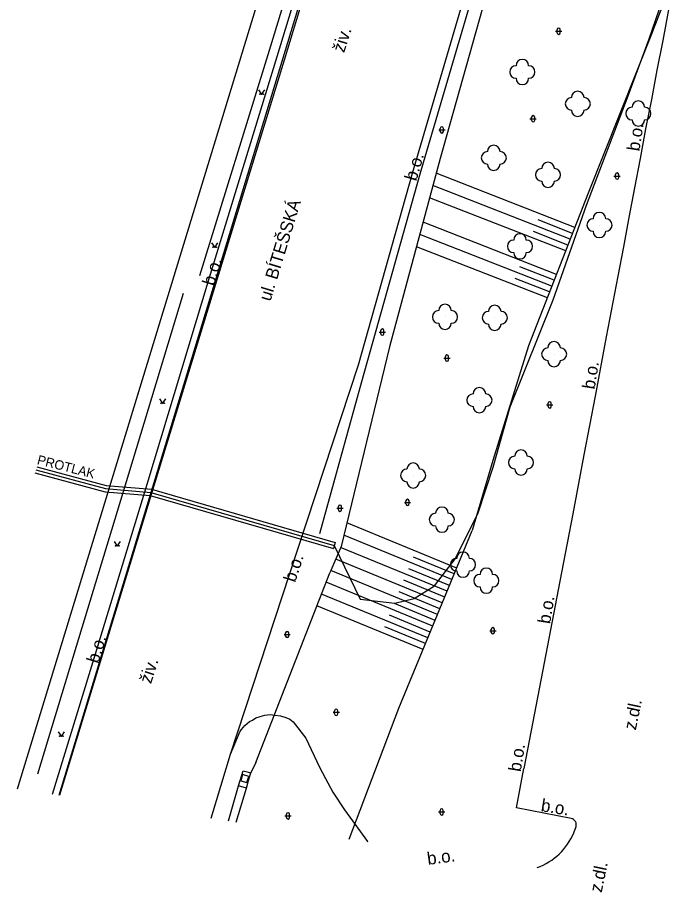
# Model space of a CAD drawing. Extents: x -601602 to -600882, y -1162594 to -1161950.
# Drawn here: x -601602.4 to -601549.7, y -1162371.2 to -1162301.7 of the extents above; entities that cross this region are included whole.
import ezdxf

# ---------------------------------------------------------------- set-up
doc = ezdxf.new("R2010")
doc.units = 0
for name, color, linetype in [('G_ZNACKY', 7, 'Continuous'), ('VRSTVA 1', 7, 'Continuous'), ('Vrstva 13', 7, 'Continuous'), ('Vrstva 14', 7, 'Continuous'), ('Vrstva 15 (Construction)', 7, 'Continuous'), ('Vrstva 16', 7, 'Continuous'), ('VRSTVA 3', 7, 'Continuous'), ('VRSTVA 5', 7, 'Continuous'), ('Vrstva 6', 7, 'Continuous'), ('Vrstva 8', 7, 'Continuous')]:
    doc.layers.add(name, color=color, linetype=linetype)

msp = doc.modelspace()

# ---------------------------------------------------------------- linework, layer by layer
at = {"layer": 'G_ZNACKY'}
for p, q in [((-601584.55, -1162361.838), (-601584.695, -1162362.317)), ((-601584.071, -1162361.983), (-601584.55, -1162361.838)), ((-601584.216, -1162362.462), (-601584.071, -1162361.983)), ((-601584.695, -1162362.317), (-601584.216, -1162362.462))]:
    msp.add_line(p, q, dxfattribs=at)
at = {"layer": 'VRSTVA 1'}
msp.add_lwpolyline([(-601600.969, -1162337.616), (-601595.43, -1162339.11), (-601591.84, -1162339.41), (-601577.27, -1162343.63), (-601575.23, -1162347.89), (-601572.47, -1162348.22), (-601570.93, -1162347.84), (-601569.32, -1162346.84), (-601567.66, -1162344.67), (-601565.85, -1162341.04), (-601564.67, -1162337.39), (-601563.31, -1162332.6), (-601559.89, -1162324.11), (-601557.24, -1162316.58), (-601553.94, -1162307.88), (-601552.28, -1162303.36), (-601551.21, -1162300.27)], dxfattribs=at)
at = {"layer": 'Vrstva 13'}
for p, q in [((-601602.424, -1162362.969), (-601579.44, -1162287.64)), ((-601599.105, -1162363.472), (-601576.28, -1162288.19)), ((-601576.41, -1162289.16), (-601581.25, -1162305.05)), ((-601571.05, -1162314.04), (-601566.41, -1162298.21)), ((-601550.65, -1162300.61), (-601551.19, -1162303.49)), ((-601551.19, -1162303.49), (-601551.66, -1162305.84)), ((-601581.25, -1162305.05), (-601586.6, -1162322.52)), ((-601551.66, -1162305.84), (-601552.09, -1162308.18)), ((-601552.09, -1162308.18), (-601552.55, -1162310.51)), ((-601552.55, -1162310.51), (-601552.99, -1162312.87)), ((-601552.99, -1162312.87), (-601553.43, -1162315.2)), ((-601575.35, -1162329.26), (-601571.05, -1162314.04)), ((-601553.43, -1162315.2), (-601553.88, -1162317.55)), ((-601553.88, -1162317.55), (-601554.32, -1162319.88)), ((-601554.32, -1162319.88), (-601554.76, -1162322.22)), ((-601554.76, -1162322.22), (-601555.68, -1162327.05)), ((-601586.6, -1162322.52), (-601591.59, -1162338.89)), ((-601555.68, -1162327.05), (-601556.57, -1162331.75)), ((-601580.79, -1162345.84), (-601575.35, -1162329.26)), ((-601556.57, -1162331.75), (-601557.46, -1162336.42)), ((-601557.46, -1162336.42), (-601558.34, -1162341.1)), ((-601591.59, -1162338.89), (-601599.094, -1162363.473)), ((-601558.34, -1162341.1), (-601559.24, -1162345.78)), ((-601585.52, -1162360.207), (-601580.79, -1162345.84)), ((-601559.24, -1162345.78), (-601560.6, -1162352.95)), ((-601560.6, -1162352.95), (-601561.5, -1162357.64)), ((-601583.491, -1162357.336), (-601583.159, -1162357.214)), ((-601583.159, -1162357.214), (-601582.776, -1162357.118)), ((-601582.776, -1162357.118), (-601582.375, -1162357.065)), ((-601582.375, -1162357.065), (-601581.991, -1162357.1)), ((-601581.991, -1162357.1), (-601581.547, -1162357.161)), ((-601581.547, -1162357.161), (-601581.128, -1162357.301)), ((-601584.371, -1162357.929), (-601584.197, -1162357.772)), ((-601584.197, -1162357.772), (-601583.996, -1162357.615)), ((-601583.996, -1162357.615), (-601583.77, -1162357.501)), ((-601583.77, -1162357.501), (-601583.491, -1162357.336)), ((-601581.128, -1162357.301), (-601580.814, -1162357.432)), ((-601580.814, -1162357.432), (-601580.53, -1162357.63)), ((-601580.53, -1162357.63), (-601579.54, -1162358.93)), ((-601561.5, -1162357.64), (-601562.22, -1162361.36)), ((-601585.51, -1162360.21), (-601584.75, -1162358.39)), ((-601584.75, -1162358.39), (-601584.65, -1162358.243)), ((-601584.65, -1162358.243), (-601584.371, -1162357.929)), ((-601579.54, -1162358.93), (-601578.452, -1162361.252)), ((-601587.055, -1162365.298), (-601585.51, -1162360.21)), ((-601578.452, -1162361.252), (-601577.963, -1162362.142)), ((-601562.81, -1162364.48), (-601562.22, -1162361.36)), ((-601584.88, -1162362.73), (-601584.52, -1162361.54)), ((-601584.52, -1162361.54), (-601583.91, -1162361.69)), ((-601584.083, -1162362.309), (-601583.91, -1162361.69)), ((-601585.662, -1162365.509), (-601584.88, -1162362.73)), ((-601584.25, -1162362.91), (-601584.88, -1162362.73)), ((-601584.25, -1162362.91), (-601584.083, -1162362.309)), ((-601577.963, -1162362.142), (-601577.388, -1162363.223)), ((-601585.053, -1162365.602), (-601584.25, -1162362.91)), ((-601577.388, -1162363.223), (-601576.464, -1162364.636)), ((-601576.464, -1162364.636), (-601575.627, -1162365.804)), ((-601558.47, -1162365.33), (-601562.81, -1162364.48)), ((-601575.627, -1162365.804), (-601574.633, -1162367.147)), ((-601558.26, -1162366.46), (-601558.08, -1162365.97)), ((-601574.633, -1162367.147), (-601574.602, -1162367.185))]:
    msp.add_line(p, q, dxfattribs=at)
for centre, radius, start, end in [((-601558.541, -1162365.812), 0.487, 341.0513, 81.66287), ((-601562.827, -1162364.569), 4.943, 289.71035, 337.51017)]:
    msp.add_arc(centre, radius, start, end, dxfattribs=at)
at = {"layer": 'Vrstva 14'}
for p, q in [((-601564.31, -1162296.62), (-601568.86, -1162312.86)), ((-601559.703, -1162302.757), (-601559.203, -1162302.757)), ((-601559.578, -1162302.882), (-601559.578, -1162302.632)), ((-601559.328, -1162302.882), (-601559.328, -1162302.632)), ((-601552.04, -1162302.86), (-601557.11, -1162315.64)), ((-601561.735, -1162309.71), (-601561.235, -1162309.71)), ((-601561.61, -1162309.835), (-601561.61, -1162309.585)), ((-601561.36, -1162309.835), (-601561.36, -1162309.585)), ((-601568.982, -1162310.602), (-601568.482, -1162310.602)), ((-601568.857, -1162310.727), (-601568.857, -1162310.477)), ((-601568.607, -1162310.727), (-601568.607, -1162310.477)), ((-601568.86, -1162312.86), (-601572.88, -1162327.83)), ((-601558.172, -1162318.355), (-601569.18, -1162314.05)), ((-601555.068, -1162314.269), (-601554.568, -1162314.269)), ((-601554.943, -1162314.394), (-601554.943, -1162314.144)), ((-601554.693, -1162314.394), (-601554.693, -1162314.144)), ((-601558.536, -1162319.286), (-601569.441, -1162315.022)), ((-601558.9, -1162320.218), (-601569.702, -1162315.994)), ((-601557.11, -1162315.64), (-601561.85, -1162327.76)), ((-601559.629, -1162322.08), (-601570.223, -1162317.937)), ((-601558.354, -1162318.821), (-601561.091, -1162317.75)), ((-601559.993, -1162323.012), (-601570.484, -1162318.909)), ((-601558.718, -1162319.752), (-601561.455, -1162318.682)), ((-601560.357, -1162323.943), (-601570.745, -1162319.881)), ((-601559.811, -1162322.546), (-601562.548, -1162321.476)), ((-601560.175, -1162323.477), (-601562.912, -1162322.407)), ((-601573.582, -1162326.794), (-601573.582, -1162326.544)), ((-601573.332, -1162326.794), (-601573.332, -1162326.544)), ((-601573.707, -1162326.669), (-601573.207, -1162326.669)), ((-601572.88, -1162327.83), (-601576.74, -1162343.71)), ((-601561.85, -1162327.76), (-601564.68, -1162336.86)), ((-601568.456, -1162328.863), (-601568.456, -1162328.613)), ((-601568.206, -1162328.863), (-601568.206, -1162328.613)), ((-601568.581, -1162328.738), (-601568.081, -1162328.738)), ((-601560.418, -1162332.451), (-601559.918, -1162332.451)), ((-601560.293, -1162332.576), (-601560.293, -1162332.326)), ((-601560.043, -1162332.576), (-601560.043, -1162332.326)), ((-601564.68, -1162336.86), (-601566.32, -1162342.43)), ((-601571.711, -1162340.204), (-601571.211, -1162340.204)), ((-601571.586, -1162340.329), (-601571.586, -1162340.079)), ((-601571.336, -1162340.329), (-601571.336, -1162340.079)), ((-601577.073, -1162340.664), (-601576.573, -1162340.664)), ((-601576.948, -1162340.789), (-601576.948, -1162340.539)), ((-601576.698, -1162340.789), (-601576.698, -1162340.539)), ((-601567.552, -1162345.418), (-601576.281, -1162341.82)), ((-601572.14, -1162356.55), (-601566.32, -1162342.43)), ((-601567.933, -1162346.343), (-601576.52, -1162342.804)), ((-601576.74, -1162343.71), (-601577.63, -1162345.8)), ((-601568.314, -1162347.267), (-601576.77, -1162343.781)), ((-601567.742, -1162345.881), (-601570.98, -1162344.546)), ((-601568.695, -1162348.192), (-601577.162, -1162344.702)), ((-601583.5, -1162360.87), (-601577.63, -1162345.8)), ((-601569.076, -1162349.117), (-601577.554, -1162345.622)), ((-601568.123, -1162346.805), (-601571.361, -1162345.471)), ((-601569.457, -1162350.041), (-601577.923, -1162346.551)), ((-601568.504, -1162347.73), (-601571.742, -1162346.395)), ((-601568.886, -1162348.654), (-601572.123, -1162347.32)), ((-601569.838, -1162350.966), (-601578.286, -1162347.484)), ((-601570.219, -1162351.89), (-601578.649, -1162348.415)), ((-601569.267, -1162349.579), (-601572.504, -1162348.245)), ((-601569.648, -1162350.503), (-601572.885, -1162349.169)), ((-601570.029, -1162351.428), (-601573.266, -1162350.094)), ((-601581.265, -1162350.702), (-601580.765, -1162350.702)), ((-601581.14, -1162350.827), (-601581.14, -1162350.577)), ((-601580.89, -1162350.827), (-601580.89, -1162350.577)), ((-601564.933, -1162350.407), (-601564.433, -1162350.407)), ((-601564.808, -1162350.532), (-601564.808, -1162350.282)), ((-601564.558, -1162350.532), (-601564.558, -1162350.282)), ((-601577.372, -1162356.885), (-601576.872, -1162356.885)), ((-601577.247, -1162357.01), (-601577.247, -1162356.76)), ((-601576.997, -1162357.01), (-601576.997, -1162356.76)), ((-601576.082, -1162366.961), (-601572.14, -1162356.55)), ((-601583.5, -1162360.87), (-601583.91, -1162361.69)), ((-601568.991, -1162364.805), (-601568.491, -1162364.805)), ((-601568.866, -1162364.93), (-601568.866, -1162364.68)), ((-601568.616, -1162364.93), (-601568.616, -1162364.68)), ((-601581.191, -1162365.114), (-601580.691, -1162365.114)), ((-601581.066, -1162365.239), (-601581.066, -1162364.989)), ((-601580.816, -1162365.239), (-601580.816, -1162364.989))]:
    msp.add_line(p, q, dxfattribs=at)
for centre in [(-601562.34, -1162306), (-601557.94, -1162308.53), (-601553.13, -1162309.3), (-601564.61, -1162312.82), (-601560.3, -1162314.17), (-601556.22, -1162318.16), (-601562.53, -1162319.85), (-601568.48, -1162325.46), (-601564.53, -1162325.53), (-601559.82, -1162328.42), (-601565.75, -1162332.08), (-601562.45, -1162337.03), (-601571.01, -1162338.06), (-601568.73, -1162341.57), (-601567.05, -1162345.15), (-601565.2, -1162346.42)]:
    msp.add_circle(centre, 0.0005, dxfattribs=at)
for centre, radius, start, end in [((-601523.195, -1162313.204), 30.643, 133.91725, 160.27226), ((-601559.453, -1162302.632), 0.125, 0, 179.99999), ((-601559.453, -1162302.882), 0.125, 179.99999, 359.99999), ((-601562.34, -1162305.5), 0.5, 0, 179.99999), ((-601562.84, -1162306), 0.5, 89.99999, 269.99999), ((-601561.84, -1162306), 0.5, 270, 89.99999), ((-601562.34, -1162306.5), 0.5, 179.99999, 359.99999), ((-601557.94, -1162308.03), 0.5, 0, 179.99999), ((-601558.44, -1162308.53), 0.5, 89.99999, 269.99999), ((-601557.44, -1162308.53), 0.5, 270, 89.99999), ((-601553.13, -1162308.8), 0.5, 0, 179.99999), ((-601557.94, -1162309.03), 0.5, 179.99999, 359.99999), ((-601553.63, -1162309.3), 0.5, 89.99999, 269.99999), ((-601552.63, -1162309.3), 0.5, 270, 89.99999), ((-601561.485, -1162309.585), 0.125, 0, 179.99999), ((-601561.485, -1162309.835), 0.125, 179.99999, 359.99999), ((-601553.13, -1162309.8), 0.5, 179.99999, 359.99999), ((-601568.731, -1162310.477), 0.125, 0, 179.99999), ((-601568.731, -1162310.727), 0.125, 179.99999, 359.99999), ((-601564.61, -1162312.32), 0.5, 0, 179.99999), ((-601565.11, -1162312.82), 0.5, 89.99999, 269.99999), ((-601564.11, -1162312.82), 0.5, 270, 89.99999), ((-601564.61, -1162313.32), 0.5, 179.99999, 359.99999), ((-601560.3, -1162313.67), 0.5, 0, 179.99999), ((-601560.8, -1162314.17), 0.5, 89.99999, 269.99999), ((-601559.8, -1162314.17), 0.5, 270, 89.99999), ((-601554.818, -1162314.144), 0.125, 0, 179.99999), ((-601560.3, -1162314.67), 0.5, 179.99999, 359.99999), ((-601554.818, -1162314.394), 0.125, 179.99999, 359.99999), ((-601556.22, -1162317.66), 0.5, 0, 179.99999), ((-601556.72, -1162318.16), 0.5, 89.99999, 269.99999), ((-601555.72, -1162318.16), 0.5, 270, 89.99999), ((-601562.53, -1162319.35), 0.5, 0, 179.99999), ((-601556.22, -1162318.66), 0.5, 179.99999, 359.99999), ((-601563.03, -1162319.85), 0.5, 89.99999, 269.99999), ((-601562.03, -1162319.85), 0.5, 270, 89.99999), ((-601562.53, -1162320.35), 0.5, 179.99999, 359.99999), ((-601568.48, -1162324.96), 0.5, 0, 179.99999), ((-601564.53, -1162325.03), 0.5, 0, 179.99999), ((-601568.98, -1162325.46), 0.5, 89.99999, 269.99999), ((-601567.98, -1162325.46), 0.5, 270, 89.99999), ((-601565.03, -1162325.53), 0.5, 89.99999, 269.99999), ((-601564.03, -1162325.53), 0.5, 270, 89.99999), ((-601573.457, -1162326.544), 0.125, 0, 179.99999), ((-601568.48, -1162325.96), 0.5, 179.99999, 359.99999), ((-601564.53, -1162326.03), 0.5, 179.99999, 359.99999), ((-601573.457, -1162326.794), 0.125, 179.99999, 359.99999), ((-601560.32, -1162328.42), 0.5, 89.99999, 269.99999), ((-601559.82, -1162327.92), 0.5, 0, 179.99999), ((-601559.32, -1162328.42), 0.5, 270, 89.99999), ((-601568.331, -1162328.613), 0.125, 0, 179.99999), ((-601568.331, -1162328.863), 0.125, 179.99999, 359.99999), ((-601559.82, -1162328.92), 0.5, 179.99999, 359.99999), ((-601565.75, -1162331.58), 0.5, 0, 179.99999), ((-601566.25, -1162332.08), 0.5, 89.99999, 269.99999), ((-601565.25, -1162332.08), 0.5, 270, 89.99999), ((-601565.75, -1162332.58), 0.5, 179.99999, 359.99999), ((-601560.168, -1162332.326), 0.125, 0, 179.99999), ((-601560.168, -1162332.576), 0.125, 179.99999, 359.99999), ((-601562.45, -1162336.53), 0.5, 0, 179.99999), ((-601562.95, -1162337.03), 0.5, 89.99999, 269.99999), ((-601561.95, -1162337.03), 0.5, 270, 89.99999), ((-601571.51, -1162338.06), 0.5, 89.99999, 269.99999), ((-601571.01, -1162337.56), 0.5, 0, 179.99999), ((-601570.51, -1162338.06), 0.5, 270, 89.99999), ((-601562.45, -1162337.53), 0.5, 179.99999, 359.99999), ((-601571.01, -1162338.56), 0.5, 179.99999, 359.99999), ((-601576.823, -1162340.539), 0.125, 0, 179.99999), ((-601571.46, -1162340.081), 0.125, 0, 179.99999), ((-601571.46, -1162340.331), 0.125, 179.99999, 359.99999), ((-601576.823, -1162340.789), 0.125, 179.99999, 359.99999), ((-601569.23, -1162341.57), 0.5, 89.99999, 269.99999), ((-601568.73, -1162341.07), 0.5, 0, 179.99999), ((-601568.23, -1162341.57), 0.5, 270, 89.99999), ((-601568.73, -1162342.07), 0.5, 179.99999, 359.99999), ((-601567.55, -1162345.15), 0.5, 89.99999, 269.99999), ((-601567.05, -1162344.65), 0.5, 0, 179.99999), ((-601566.55, -1162345.15), 0.5, 270, 89.99999), ((-601567.05, -1162345.65), 0.5, 179.99999, 359.99999), ((-601565.7, -1162346.42), 0.5, 89.99999, 269.99999), ((-601565.2, -1162345.92), 0.5, 0, 179.99999), ((-601564.7, -1162346.42), 0.5, 270, 89.99999), ((-601565.2, -1162346.92), 0.5, 179.99999, 359.99999), ((-601564.683, -1162350.282), 0.125, 0, 179.99999), ((-601581.015, -1162350.577), 0.125, 0, 179.99999), ((-601581.015, -1162350.827), 0.125, 179.99999, 359.99999), ((-601564.683, -1162350.532), 0.125, 179.99999, 359.99999), ((-601577.122, -1162356.76), 0.125, 0, 179.99999), ((-601577.122, -1162357.01), 0.125, 179.99999, 359.99999), ((-601580.941, -1162364.989), 0.125, 0, 179.99999), ((-601568.741, -1162364.68), 0.125, 0, 179.99999), ((-601580.941, -1162365.239), 0.125, 179.99999, 359.99999), ((-601568.741, -1162364.93), 0.125, 179.99999, 359.99999)]:
    msp.add_arc(centre, radius, start, end, dxfattribs=at)
at = {"layer": 'VRSTVA 3'}
for points in [[(-601583.299, -1162307.412), (-601583.049, -1162307.787), (-601582.799, -1162307.412)], [(-601587.02, -1162319.57), (-601586.77, -1162319.945), (-601586.52, -1162319.57)], [(-601591.155, -1162331.975), (-601590.905, -1162332.35), (-601590.655, -1162331.975)], [(-601594.758, -1162343.308), (-601594.508, -1162343.683), (-601594.258, -1162343.308)], [(-601599.188, -1162358.426), (-601598.938, -1162358.801), (-601598.688, -1162358.426)]]:
    msp.add_lwpolyline(points, dxfattribs=at)
for centre in [(-601583.174, -1162307.762), (-601582.924, -1162307.762), (-601586.895, -1162319.92), (-601586.645, -1162319.92), (-601591.03, -1162332.325), (-601590.78, -1162332.325), (-601594.633, -1162343.658), (-601594.383, -1162343.658), (-601599.063, -1162358.776), (-601598.813, -1162358.776)]:
    msp.add_circle(centre, 0.025, dxfattribs=at)
at = {"layer": 'VRSTVA 5'}
msp.add_line((-601577.2, -1162343.39), (-601577.34, -1162343.87), dxfattribs=at)
for points in [[(-601600.969, -1162337.616), (-601595.43, -1162339.11), (-601591.84, -1162339.41), (-601577.27, -1162343.63)], [(-601600.896, -1162337.377), (-601595.387, -1162338.863), (-601591.794, -1162339.163), (-601577.2, -1162343.39)], [(-601601.041, -1162337.856), (-601595.473, -1162339.357), (-601591.886, -1162339.657), (-601577.34, -1162343.87)]]:
    msp.add_lwpolyline(points, dxfattribs=at)
at = {"layer": 'Vrstva 8'}
for p, q in [((-601582.43, -1162304.26), (-601577.72, -1162288.88)), ((-601581.81, -1162304.76), (-601576.98, -1162289.05)), ((-601565.84, -1162298.35), (-601570.47, -1162314.11)), ((-601587.96, -1162322.18), (-601582.43, -1162304.26)), ((-601587.2, -1162322.42), (-601581.81, -1162304.76)), ((-601570.47, -1162314.11), (-601575.12, -1162330.61)), ((-601592.12, -1162338.75), (-601587.2, -1162322.42)), ((-601589.26, -1162323.61), (-601593.6, -1162337.95)), ((-601575.12, -1162330.61), (-601578.46, -1162342.69)), ((-601593.6, -1162337.95), (-601597.78, -1162351.66)), ((-601596.22, -1162352.25), (-601592.12, -1162338.75)), ((-601597.78, -1162351.66), (-601600.84, -1162361.79)), ((-601599.652, -1162363.389), (-601596.22, -1162352.25))]:
    msp.add_line(p, q, dxfattribs=at)

# ---------------------------------------------------------------- texts
at = {"layer": 'Vrstva 15 (Construction)'}
msp.add_text('ul. BÍTEŠSKÁ', height=1, rotation=73.05284, dxfattribs=at).set_placement((-601582.344, -1162324.271))
at = {"layer": 'Vrstva 16'}
for s, rotation, p in [('živ.', 72.13812, (-601576.498, -1162304.517)), ('b.o.', 80.89294, (-601553.054, -1162312.338)), ('b.o.', 73.47991, (-601570.768, -1162314.722)), ('b.o.', 73.01275, (-601586.827, -1162323.053)), ('b.o.', 80.89294, (-601556.606, -1162331.261)), ('b.o.', 71.80223, (-601580.381, -1162346.615)), ('b.o.', 80.89294, (-601560.135, -1162349.901)), ('b.o.', 72.99903, (-601596.01, -1162353.056)), ('živ.', 72.13812, (-601591.829, -1162354.666)), ('z.dl.', 78.18978, (-601553.336, -1162358.343)), ('b.o.', 80.89294, (-601562.47, -1162361.652)), ('b.o.', 350.89294, (-601560.914, -1162364.736)), ('b.o.', 7.69592, (-601569.835, -1162369.015)), ('z.dl.', 78.18978, (-601556.047, -1162371.257))]:
    msp.add_text(s, height=1, rotation=rotation, dxfattribs=at).set_placement(p)
at = {"layer": 'Vrstva 6'}
msp.add_text('PROTLAK', height=0.75, rotation=345.65856, dxfattribs=at).set_placement((-601600.92, -1162337.151))

doc.saveas('drawing.dxf')
